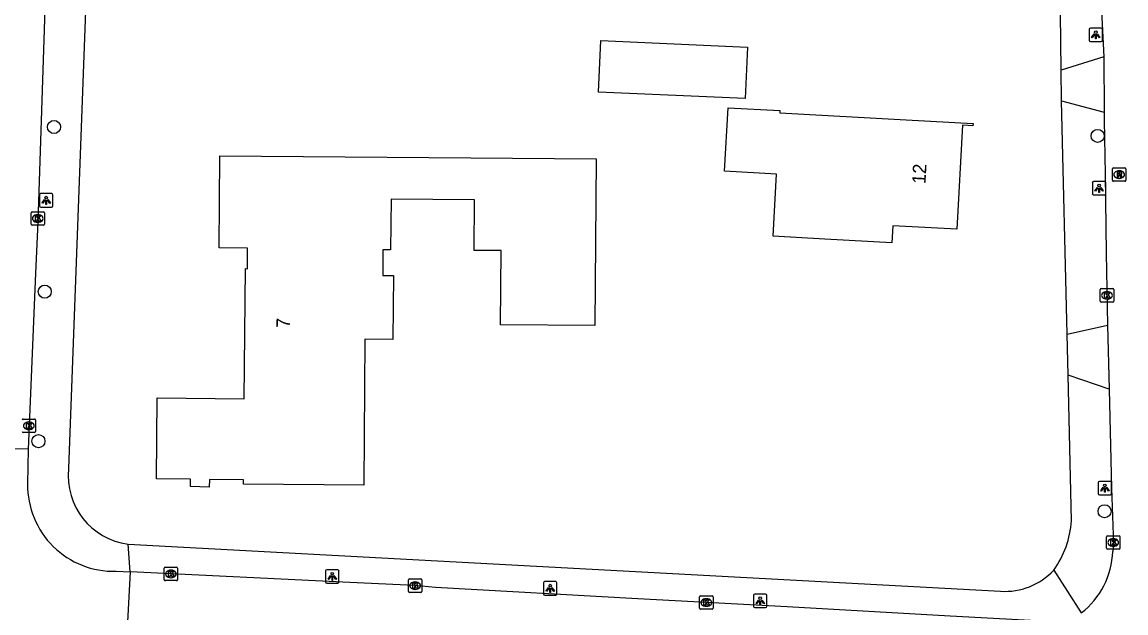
# Model space of a CAD drawing. Extents: x 161258 to 161838, y 380836 to 381727.
# Drawn here: x 161570.3 to 161652.5, y 381186.3 to 381230.3 of the extents above; entities that cross this region are included whole.
import ezdxf

# ---------------------------------------------------------------- set-up
doc = ezdxf.new("R2010")
doc.units = 0
for name, color, linetype in [('IMGEO_Boom', 7, 'Continuous'), ('IMGEO_Kolk', 7, 'Continuous'), ('IMGEO_Lichtpunt', 7, 'Continuous'), ('IMGEO_Pand', 7, 'Continuous'), ('IMGEO_Pand_nummerreeks', 7, 'Continuous'), ('IMGEO_Rijbaan_lokaal_open', 7, 'Continuous'), ('IMGEO_Rioolput', 7, 'Continuous'), ('IMGEO_Voetpad_open', 7, 'Continuous')]:
    doc.layers.add(name, color=color, linetype=linetype)

msp = doc.modelspace()

# ---------------------------------------------------------------- linework, layer by layer
at = {"layer": 'IMGEO_Boom'}
for centre in [(161572.69, 381222.454), (161650.414, 381221.789), (161571.999, 381210.202), (161571.528, 381199.077), (161650.929, 381193.862)]:
    msp.add_circle(centre, 0.489, dxfattribs=at)
at = {"layer": 'IMGEO_Kolk'}
for p, q in [((161570.979, 381215.224), (161570.979, 381216.076)), ((161571.054, 381216.15), (161571.906, 381216.15)), ((161571.467, 381215.93), (161571.492, 381215.93)), ((161571.98, 381216.076), (161571.98, 381215.224)), ((161571.906, 381215.15), (161571.054, 381215.15)), ((161571.49, 381215.37), (161571.465, 381215.37)), ((161650.609, 381209.499), (161650.609, 381210.351)), ((161650.684, 381210.425), (161651.536, 381210.425)), ((161651.097, 381210.205), (161651.122, 381210.205)), ((161651.61, 381210.351), (161651.61, 381209.499)), ((161651.536, 381209.425), (161650.684, 381209.425)), ((161651.12, 381209.645), (161651.095, 381209.645)), ((161570.387, 381200.724), (161571.239, 381200.724)), ((161571.313, 381200.65), (161571.313, 381199.798)), ((161570.823, 381199.944), (161570.798, 381199.944)), ((161570.8, 381200.504), (161570.825, 381200.504)), ((161571.239, 381199.724), (161570.387, 381199.724)), ((161651.076, 381191.107), (161651.076, 381191.959)), ((161651.151, 381192.033), (161652.003, 381192.033)), ((161651.564, 381191.813), (161651.589, 381191.813)), ((161652.077, 381191.959), (161652.077, 381191.107)), ((161652.003, 381191.033), (161651.151, 381191.033)), ((161651.587, 381191.253), (161651.562, 381191.253)), ((161580.895, 381188.771), (161580.895, 381189.623)), ((161580.97, 381189.697), (161581.822, 381189.697)), ((161581.383, 381189.477), (161581.408, 381189.477)), ((161581.896, 381189.623), (161581.896, 381188.771)), ((161581.822, 381188.697), (161580.97, 381188.697)), ((161581.406, 381188.917), (161581.381, 381188.917)), ((161599.084, 381187.9), (161599.084, 381188.752)), ((161599.159, 381188.826), (161600.011, 381188.826)), ((161599.572, 381188.606), (161599.597, 381188.606)), ((161600.085, 381188.752), (161600.085, 381187.9)), ((161600.011, 381187.826), (161599.159, 381187.826)), ((161599.595, 381188.046), (161599.57, 381188.046)), ((161620.771, 381186.642), (161620.771, 381187.494)), ((161620.846, 381187.568), (161621.698, 381187.568)), ((161621.772, 381187.494), (161621.772, 381186.642)), ((161621.282, 381186.788), (161621.257, 381186.788)), ((161621.259, 381187.348), (161621.284, 381187.348)), ((161621.698, 381186.568), (161620.846, 381186.568))]:
    msp.add_line(p, q, dxfattribs=at)
for points in [[(161570.979, 381215.224), (161570.979, 381216.076)], [(161571.054, 381216.15), (161571.906, 381216.15)], [(161571.3, 381215.85), (161571.423, 381215.85), (161571.423, 381215.699), (161571.553, 381215.85), (161571.717, 381215.85), (161571.571, 381215.699), (161571.724, 381215.45), (161571.572, 381215.45), (161571.487, 381215.614), (161571.423, 381215.547), (161571.423, 381215.45), (161571.3, 381215.45), (161571.3, 381215.85)], [(161571.98, 381216.076), (161571.98, 381215.224)], [(161571.906, 381215.15), (161571.054, 381215.15)], [(161650.609, 381209.499), (161650.609, 381210.351)], [(161650.684, 381210.425), (161651.536, 381210.425)], [(161650.93, 381210.125), (161651.053, 381210.125), (161651.053, 381209.974), (161651.183, 381210.125), (161651.347, 381210.125), (161651.201, 381209.974), (161651.354, 381209.725), (161651.202, 381209.725), (161651.117, 381209.889), (161651.053, 381209.822), (161651.053, 381209.725), (161650.93, 381209.725), (161650.93, 381210.125)], [(161651.61, 381210.351), (161651.61, 381209.499)], [(161651.536, 381209.425), (161650.684, 381209.425)], [(161570.387, 381200.724), (161571.239, 381200.724)], [(161571.313, 381200.65), (161571.313, 381199.798)], [(161570.633, 381200.424), (161570.756, 381200.424), (161570.756, 381200.273), (161570.886, 381200.424), (161571.05, 381200.424), (161570.904, 381200.273), (161571.057, 381200.024), (161570.905, 381200.024), (161570.82, 381200.188), (161570.756, 381200.121), (161570.756, 381200.024), (161570.633, 381200.024), (161570.633, 381200.424)], [(161571.239, 381199.724), (161570.387, 381199.724)], [(161651.076, 381191.107), (161651.076, 381191.959)], [(161651.151, 381192.033), (161652.003, 381192.033)], [(161651.397, 381191.733), (161651.52, 381191.733), (161651.52, 381191.582), (161651.65, 381191.733), (161651.814, 381191.733), (161651.668, 381191.582), (161651.821, 381191.333), (161651.669, 381191.333), (161651.584, 381191.497), (161651.52, 381191.43), (161651.52, 381191.333), (161651.397, 381191.333), (161651.397, 381191.733)], [(161652.077, 381191.959), (161652.077, 381191.107)], [(161652.003, 381191.033), (161651.151, 381191.033)], [(161580.895, 381188.771), (161580.895, 381189.623)], [(161580.97, 381189.697), (161581.822, 381189.697)], [(161581.216, 381189.397), (161581.339, 381189.397), (161581.339, 381189.246), (161581.469, 381189.397), (161581.633, 381189.397), (161581.487, 381189.246), (161581.64, 381188.997), (161581.488, 381188.997), (161581.403, 381189.161), (161581.339, 381189.094), (161581.339, 381188.997), (161581.216, 381188.997), (161581.216, 381189.397)], [(161581.896, 381189.623), (161581.896, 381188.771)], [(161581.822, 381188.697), (161580.97, 381188.697)], [(161599.084, 381187.9), (161599.084, 381188.752)], [(161599.159, 381188.826), (161600.011, 381188.826)], [(161599.405, 381188.526), (161599.528, 381188.526), (161599.528, 381188.375), (161599.658, 381188.526), (161599.822, 381188.526), (161599.676, 381188.375), (161599.829, 381188.126), (161599.677, 381188.126), (161599.592, 381188.29), (161599.528, 381188.223), (161599.528, 381188.126), (161599.405, 381188.126), (161599.405, 381188.526)], [(161600.085, 381188.752), (161600.085, 381187.9)], [(161600.011, 381187.826), (161599.159, 381187.826)], [(161620.771, 381186.642), (161620.771, 381187.494)], [(161620.846, 381187.568), (161621.698, 381187.568)], [(161621.772, 381187.494), (161621.772, 381186.642)], [(161621.092, 381187.268), (161621.215, 381187.268), (161621.215, 381187.117), (161621.345, 381187.268), (161621.509, 381187.268), (161621.363, 381187.117), (161621.516, 381186.868), (161621.364, 381186.868), (161621.279, 381187.032), (161621.215, 381186.965), (161621.215, 381186.868), (161621.092, 381186.868), (161621.092, 381187.268)], [(161621.698, 381186.568), (161620.846, 381186.568)]]:
    msp.add_lwpolyline(points, dxfattribs=at)
for centre, start, end in [((161571.056, 381216.074), 91.55205, 178.44795), ((161571.056, 381216.074), 91.55205, 178.44795), ((161571.904, 381216.074), 1.55205, 88.44795), ((161571.904, 381216.074), 1.55205, 88.44795), ((161571.056, 381215.226), 181.55205, 268.44795), ((161571.056, 381215.226), 181.55205, 268.44795), ((161571.904, 381215.226), 271.55205, 358.44795), ((161571.904, 381215.226), 271.55205, 358.44795), ((161650.686, 381210.349), 91.55205, 178.44795), ((161650.686, 381210.349), 91.55205, 178.44795), ((161651.534, 381210.349), 1.55205, 88.44795), ((161651.534, 381210.349), 1.55205, 88.44795), ((161650.686, 381209.501), 181.55205, 268.44795), ((161650.686, 381209.501), 181.55205, 268.44795), ((161651.534, 381209.501), 271.55205, 358.44795), ((161651.534, 381209.501), 271.55205, 358.44795), ((161570.389, 381200.648), 91.55205, 178.44795), ((161570.389, 381200.648), 91.55205, 178.44795), ((161571.237, 381200.648), 1.55205, 88.44795), ((161571.237, 381200.648), 1.55205, 88.44795), ((161570.389, 381199.8), 181.55205, 268.44795), ((161570.389, 381199.8), 181.55205, 268.44795), ((161571.237, 381199.8), 271.55205, 358.44795), ((161571.237, 381199.8), 271.55205, 358.44795), ((161651.153, 381191.957), 91.55205, 178.44795), ((161651.153, 381191.957), 91.55205, 178.44795), ((161652.001, 381191.957), 1.55205, 88.44795), ((161652.001, 381191.957), 1.55205, 88.44795), ((161651.153, 381191.109), 181.55205, 268.44795), ((161651.153, 381191.109), 181.55205, 268.44795), ((161652.001, 381191.109), 271.55205, 358.44795), ((161652.001, 381191.109), 271.55205, 358.44795), ((161580.972, 381189.621), 91.55205, 178.44795), ((161580.972, 381189.621), 91.55205, 178.44795), ((161581.82, 381189.621), 1.55205, 88.44795), ((161581.82, 381189.621), 1.55205, 88.44795), ((161580.972, 381188.773), 181.55205, 268.44795), ((161580.972, 381188.773), 181.55205, 268.44795), ((161581.82, 381188.773), 271.55205, 358.44795), ((161581.82, 381188.773), 271.55205, 358.44795), ((161599.161, 381188.75), 91.55205, 178.44795), ((161599.161, 381188.75), 91.55205, 178.44795), ((161600.009, 381188.75), 1.55205, 88.44795), ((161600.009, 381188.75), 1.55205, 88.44795), ((161599.161, 381187.902), 181.55205, 268.44795), ((161599.161, 381187.902), 181.55205, 268.44795), ((161600.009, 381187.902), 271.55205, 358.44795), ((161600.009, 381187.902), 271.55205, 358.44795), ((161620.848, 381187.492), 91.55205, 178.44795), ((161620.848, 381187.492), 91.55205, 178.44795), ((161621.696, 381187.492), 1.55205, 88.44795), ((161621.696, 381187.492), 1.55205, 88.44795), ((161620.848, 381186.644), 181.55205, 268.44795), ((161620.848, 381186.644), 181.55205, 268.44795), ((161621.696, 381186.644), 271.55205, 358.44795), ((161621.696, 381186.644), 271.55205, 358.44795)]:
    msp.add_arc(centre, 0.0765, start, end, dxfattribs=at)
for centre, major_axis, ratio, start_param, end_param in [((161571.466, 381215.65), (-0.387, 0.002), 0.722429, 4.712389, 7.853982), ((161571.491, 381215.65), (-0.39, 0.002), 0.717154, 1.570796, 4.712389), ((161651.096, 381209.925), (-0.387, 0.002), 0.722429, 4.712389, 7.853982), ((161651.121, 381209.925), (-0.39, 0.002), 0.717154, 1.570796, 4.712389), ((161570.799, 381200.224), (-0.387, 0.002), 0.722429, 4.712389, 7.853982), ((161570.824, 381200.224), (-0.39, 0.002), 0.717154, 1.570796, 4.712389), ((161651.563, 381191.533), (-0.387, 0.002), 0.722429, 4.712389, 7.853982), ((161651.588, 381191.533), (-0.39, 0.002), 0.717154, 1.570796, 4.712389), ((161581.382, 381189.197), (-0.387, 0.002), 0.722429, 4.712389, 7.853982), ((161581.407, 381189.197), (-0.39, 0.002), 0.717154, 1.570796, 4.712389), ((161599.571, 381188.326), (-0.387, 0.002), 0.722429, 4.712389, 7.853982), ((161599.596, 381188.326), (-0.39, 0.002), 0.717154, 1.570796, 4.712389), ((161621.258, 381187.068), (-0.387, 0.002), 0.722429, 4.712389, 7.853982), ((161621.283, 381187.068), (-0.39, 0.002), 0.717154, 1.570796, 4.712389)]:
    msp.add_ellipse(centre, major_axis=major_axis, ratio=ratio, start_param=start_param, end_param=end_param, dxfattribs=at)
at = {"layer": 'IMGEO_Lichtpunt'}
for p, q in [((161649.775, 381229.71), (161649.775, 381228.903)), ((161649.775, 381229.71), (161649.775, 381228.903)), ((161650.677, 381229.805), (161649.869, 381229.805)), ((161650.677, 381229.805), (161649.869, 381229.805)), ((161650.771, 381228.903), (161650.771, 381229.71)), ((161650.771, 381228.903), (161650.771, 381229.71)), ((161649.869, 381228.809), (161650.677, 381228.809)), ((161649.869, 381228.809), (161650.677, 381228.809)), ((161650.017, 381218.295), (161650.017, 381217.488)), ((161650.017, 381218.295), (161650.017, 381217.488)), ((161650.919, 381218.39), (161650.111, 381218.39)), ((161650.919, 381218.39), (161650.111, 381218.39)), ((161651.013, 381217.488), (161651.013, 381218.295)), ((161651.013, 381217.488), (161651.013, 381218.295)), ((161571.61, 381217.399), (161571.61, 381216.592)), ((161571.61, 381217.399), (161571.61, 381216.592)), ((161572.512, 381217.494), (161571.704, 381217.494)), ((161572.512, 381217.494), (161571.704, 381217.494)), ((161572.606, 381216.592), (161572.606, 381217.399)), ((161572.606, 381216.592), (161572.606, 381217.399)), ((161650.111, 381217.394), (161650.919, 381217.394)), ((161650.111, 381217.394), (161650.919, 381217.394)), ((161571.704, 381216.498), (161572.512, 381216.498)), ((161571.704, 381216.498), (161572.512, 381216.498)), ((161650.456, 381195.99), (161650.456, 381195.183)), ((161650.456, 381195.99), (161650.456, 381195.183)), ((161651.358, 381196.085), (161650.55, 381196.085)), ((161651.358, 381196.085), (161650.55, 381196.085)), ((161651.452, 381195.183), (161651.452, 381195.99)), ((161651.452, 381195.183), (161651.452, 381195.99)), ((161650.55, 381195.089), (161651.358, 381195.089)), ((161650.55, 381195.089), (161651.358, 381195.089)), ((161592.918, 381189.417), (161592.918, 381188.61)), ((161592.918, 381189.417), (161592.918, 381188.61)), ((161593.82, 381189.512), (161593.012, 381189.512)), ((161593.82, 381189.512), (161593.012, 381189.512)), ((161593.914, 381188.61), (161593.914, 381189.417)), ((161593.914, 381188.61), (161593.914, 381189.417)), ((161593.012, 381188.516), (161593.82, 381188.516)), ((161593.012, 381188.516), (161593.82, 381188.516)), ((161609.15, 381188.528), (161609.15, 381187.721)), ((161609.15, 381188.528), (161609.15, 381187.721)), ((161610.052, 381188.623), (161609.244, 381188.623)), ((161610.052, 381188.623), (161609.244, 381188.623)), ((161610.146, 381187.721), (161610.146, 381188.528)), ((161610.146, 381187.721), (161610.146, 381188.528)), ((161609.244, 381187.627), (161610.052, 381187.627)), ((161609.244, 381187.627), (161610.052, 381187.627)), ((161624.787, 381187.59), (161624.787, 381186.783)), ((161624.787, 381187.59), (161624.787, 381186.783)), ((161625.689, 381187.685), (161624.881, 381187.685)), ((161625.689, 381187.685), (161624.881, 381187.685)), ((161625.783, 381186.783), (161625.783, 381187.59)), ((161625.783, 381186.783), (161625.783, 381187.59)), ((161624.881, 381186.689), (161625.689, 381186.689)), ((161624.881, 381186.689), (161625.689, 381186.689))]:
    msp.add_line(p, q, dxfattribs=at)
for points in [[(161650.149, 381229.374), (161650.188, 381229.346), (161650, 381229.084), (161649.962, 381229.111), (161650.149, 381229.374)], [(161650.251, 381229.326), (161650.298, 381229.326), (161650.298, 381229.004), (161650.251, 381229.004), (161650.251, 381229.326)], [(161650.361, 381229.346), (161650.399, 381229.373), (161650.586, 381229.111), (161650.547, 381229.083), (161650.361, 381229.346)], [(161650.391, 381217.959), (161650.43, 381217.931), (161650.242, 381217.669), (161650.204, 381217.696), (161650.391, 381217.959)], [(161650.493, 381217.911), (161650.54, 381217.911), (161650.54, 381217.589), (161650.493, 381217.589), (161650.493, 381217.911)], [(161650.603, 381217.931), (161650.641, 381217.958), (161650.828, 381217.696), (161650.789, 381217.668), (161650.603, 381217.931)], [(161571.984, 381217.063), (161572.023, 381217.035), (161571.835, 381216.773), (161571.797, 381216.8), (161571.984, 381217.063)], [(161572.196, 381217.035), (161572.234, 381217.062), (161572.421, 381216.8), (161572.382, 381216.772), (161572.196, 381217.035)], [(161572.086, 381217.015), (161572.133, 381217.015), (161572.133, 381216.693), (161572.086, 381216.693), (161572.086, 381217.015)], [(161650.83, 381195.654), (161650.869, 381195.626), (161650.681, 381195.364), (161650.643, 381195.391), (161650.83, 381195.654)], [(161650.932, 381195.606), (161650.979, 381195.606), (161650.979, 381195.284), (161650.932, 381195.284), (161650.932, 381195.606)], [(161651.042, 381195.626), (161651.08, 381195.653), (161651.267, 381195.391), (161651.228, 381195.363), (161651.042, 381195.626)], [(161593.292, 381189.081), (161593.331, 381189.053), (161593.143, 381188.791), (161593.105, 381188.818), (161593.292, 381189.081)], [(161593.394, 381189.033), (161593.441, 381189.033), (161593.441, 381188.711), (161593.394, 381188.711), (161593.394, 381189.033)], [(161593.504, 381189.053), (161593.542, 381189.08), (161593.729, 381188.818), (161593.69, 381188.79), (161593.504, 381189.053)], [(161609.524, 381188.192), (161609.563, 381188.164), (161609.375, 381187.902), (161609.337, 381187.929), (161609.524, 381188.192)], [(161609.626, 381188.144), (161609.673, 381188.144), (161609.673, 381187.822), (161609.626, 381187.822), (161609.626, 381188.144)], [(161609.736, 381188.164), (161609.774, 381188.191), (161609.961, 381187.929), (161609.922, 381187.901), (161609.736, 381188.164)], [(161625.161, 381187.254), (161625.2, 381187.226), (161625.012, 381186.964), (161624.974, 381186.991), (161625.161, 381187.254)], [(161625.263, 381187.206), (161625.31, 381187.206), (161625.31, 381186.884), (161625.263, 381186.884), (161625.263, 381187.206)], [(161625.373, 381187.226), (161625.411, 381187.253), (161625.598, 381186.991), (161625.559, 381186.963), (161625.373, 381187.226)]]:
    msp.add_lwpolyline(points, dxfattribs=at)
for centre in [(161650.274, 381229.508), (161650.516, 381218.093), (161572.109, 381217.197), (161650.955, 381195.788), (161593.417, 381189.215), (161609.649, 381188.326), (161625.286, 381187.388)]:
    msp.add_circle(centre, 0.0994, dxfattribs=at)
for centre, start, end in [((161649.869, 381229.71), 90, 180), ((161649.869, 381229.71), 90, 180), ((161650.677, 381229.71), 0, 90), ((161650.677, 381229.71), 0, 90), ((161649.869, 381228.903), 180, 270), ((161649.869, 381228.903), 180, 270), ((161650.677, 381228.903), 270, 0), ((161650.677, 381228.903), 270, 360), ((161650.111, 381218.295), 90, 180), ((161650.111, 381218.295), 90, 180), ((161650.919, 381218.295), 0, 90), ((161650.919, 381218.295), 0, 90), ((161571.704, 381217.399), 90, 180), ((161571.704, 381217.399), 90, 180), ((161572.512, 381217.399), 0, 90), ((161572.512, 381217.399), 0, 90), ((161650.111, 381217.488), 180, 270), ((161650.111, 381217.488), 180, 270), ((161650.919, 381217.488), 270, 0), ((161650.919, 381217.488), 270, 360), ((161571.704, 381216.592), 180, 270), ((161571.704, 381216.592), 180, 270), ((161572.512, 381216.592), 270, 0), ((161572.512, 381216.592), 270, 360), ((161650.55, 381195.99), 90, 180), ((161650.55, 381195.99), 90, 180), ((161651.358, 381195.99), 0, 90), ((161651.358, 381195.99), 0, 90), ((161650.55, 381195.183), 180, 270), ((161650.55, 381195.183), 180, 270), ((161651.358, 381195.183), 270, 0), ((161651.358, 381195.183), 270, 360), ((161593.012, 381189.417), 90, 180), ((161593.012, 381189.417), 90, 180), ((161593.82, 381189.417), 0, 90), ((161593.82, 381189.417), 0, 90), ((161593.012, 381188.61), 180, 270), ((161593.012, 381188.61), 180, 270), ((161593.82, 381188.61), 270, 0), ((161593.82, 381188.61), 270, 360), ((161609.244, 381188.528), 90, 180), ((161609.244, 381188.528), 90, 180), ((161610.052, 381188.528), 0, 90), ((161610.052, 381188.528), 0, 90), ((161609.244, 381187.721), 180, 270), ((161609.244, 381187.721), 180, 270), ((161610.052, 381187.721), 270, 0), ((161610.052, 381187.721), 270, 360), ((161624.881, 381187.59), 90, 180), ((161624.881, 381187.59), 90, 180), ((161625.689, 381187.59), 0, 90), ((161625.689, 381187.59), 0, 90), ((161624.881, 381186.783), 180, 270), ((161624.881, 381186.783), 180, 270), ((161625.689, 381186.783), 270, 0), ((161625.689, 381186.783), 270, 360)]:
    msp.add_arc(centre, 0.0946, start, end, dxfattribs=at)
at = {"layer": 'IMGEO_Pand'}
for points in [[(161624.335, 381228.4), (161624.163, 381224.563), (161613.241, 381225.052), (161613.413, 381228.889), (161624.335, 381228.4)], [(161636.144, 381222.993), (161641.136, 381222.717), (161641.126, 381222.537), (161640.355, 381222.58), (161639.927, 381214.841), (161635.155, 381215.104), (161635.085, 381213.84), (161630.093, 381214.116), (161626.251, 381214.329), (161626.506, 381218.942), (161622.624, 381219.157), (161622.886, 381223.888), (161626.752, 381223.674), (161626.743, 381223.513), (161636.144, 381222.993)], [(161613.076, 381220.081), (161612.97, 381207.678), (161605.94, 381207.738), (161605.987, 381213.258), (161603.977, 381213.275), (161604.009, 381217.035), (161597.789, 381217.088), (161597.757, 381213.308), (161597.187, 381213.313), (161597.171, 381211.413), (161597.961, 381211.406), (161597.92, 381206.637), (161595.85, 381206.654), (161595.758, 381195.795), (161586.798, 381195.871), (161586.801, 381196.191), (161584.259, 381196.213), (161584.246, 381195.661), (161582.854, 381195.695), (161582.867, 381196.252), (161580.317, 381196.27), (161580.372, 381202.296), (161586.851, 381202.237), (161586.958, 381211.913), (161587.088, 381211.912), (161587.096, 381213.428), (161584.979, 381213.461), (161585.037, 381220.32), (161613.076, 381220.081)]]:
    msp.add_lwpolyline(points, dxfattribs=at)
at = {"layer": 'IMGEO_Rijbaan_lokaal_open'}
for points in [[(161571.005, 381317.713), (161571.088, 381311.972), (161571.149, 381309.659), (161571.247, 381305.925), (161571.333, 381300.008), (161571.367, 381297.22), (161571.552, 381289.803), (161571.71, 381285.385), (161571.841, 381280.385), (161571.937, 381276.234), (161572.007, 381272.353), (161572.171, 381266.916), (161572.516, 381257.53), (161572.49, 381252.317), (161572.562, 381247.819), (161571.478, 381215.409), (161571.305, 381211.541), (161570.775, 381198.479)], [(161650.551, 381240.927), (161650.682, 381233.085), (161650.693, 381231.097), (161650.875, 381227.666)], [(161650.875, 381227.666), (161650.9, 381223.559)], [(161650.9, 381223.559), (161650.904, 381222.961), (161650.974, 381218.943), (161651.056, 381213.077), (161651.149, 381207.702)], [(161651.149, 381207.702), (161651.259, 381202.942)], [(161651.259, 381202.942), (161651.452, 381195.577), (161651.582, 381191.419), (161651.539, 381190.879)], [(161570.775, 381198.479), (161563.65, 381198.628)], [(161570.775, 381198.479), (161570.721, 381195.892)], [(161577.308, 381189.397), (161578.352, 381189.346)], [(161578.352, 381189.346), (161578.149, 381185.166)], [(161646.327, 381185.682), (161639.431, 381186.067), (161627.28, 381186.753), (161616.166, 381187.333), (161601.106, 381188.192), (161599.538, 381188.329), (161594.72, 381188.551), (161578.352, 381189.346)]]:
    msp.add_lwpolyline(points, dxfattribs=at)
for centre, radius, start, end in [((161577.135, 381195.809), 6.415, 179.26189, 271.54397), ((161645.542, 381191.065), 6, 307.38392, 358.2223)]:
    msp.add_arc(centre, radius, start, end, dxfattribs=at)
at = {"layer": 'IMGEO_Rioolput'}
for p, q in [((161651.517, 381218.485), (161651.517, 381219.337)), ((161651.592, 381219.411), (161652.444, 381219.411)), ((161652.005, 381219.191), (161652.03, 381219.191)), ((161652.518, 381219.337), (161652.518, 381218.485)), ((161652.444, 381218.411), (161651.592, 381218.411)), ((161652.028, 381218.631), (161652.003, 381218.631))]:
    msp.add_line(p, q, dxfattribs=at)
for points in [[(161651.517, 381218.485), (161651.517, 381219.337)], [(161651.592, 381219.411), (161652.444, 381219.411)], [(161652.106, 381219.109), (161651.854, 381219.111), (161651.854, 381218.711)], [(161651.854, 381218.711), (161651.978, 381218.711), (161651.978, 381218.873), (161651.989, 381218.873)], [(161652.032, 381219.03), (161651.978, 381219.03), (161651.978, 381218.949)], [(161651.978, 381218.949), (161652.03, 381218.949)], [(161652.036, 381218.844), (161652.107, 381218.711), (161652.247, 381218.711), (161652.182, 381218.837)], [(161652.518, 381219.337), (161652.518, 381218.485)], [(161652.444, 381218.411), (161651.592, 381218.411)]]:
    msp.add_lwpolyline(points, dxfattribs=at)
for centre, radius, start, end in [((161651.594, 381219.335), 0.0765, 91.55205, 178.44795), ((161651.594, 381219.335), 0.0765, 91.55205, 178.44795), ((161651.988, 381218.82), 0.0533, 26.02933, 88.69889), ((161652.014, 381219.138), 0.19, 274.7715, 282.96867), ((161652.038, 381218.934), 0.0964, 77.00612, 93.18647), ((161652.052, 381218.991), 0.0378, 276.66336, 79.67722), ((161652.105, 381218.999), 0.109, 350.36119, 89.41601), ((161652.103, 381218.999), 0.112, 277.58423, 350.98172), ((161652.087, 381218.784), 0.108, 29.51342, 73.79051), ((161652.442, 381219.335), 0.0765, 1.55205, 88.44795), ((161652.442, 381219.335), 0.0765, 1.55205, 88.44795), ((161651.594, 381218.487), 0.0765, 181.55205, 268.44795), ((161651.594, 381218.487), 0.0765, 181.55205, 268.44795), ((161652.442, 381218.487), 0.0765, 271.55205, 358.44795), ((161652.442, 381218.487), 0.0765, 271.55205, 358.44795)]:
    msp.add_arc(centre, radius, start, end, dxfattribs=at)
for centre, major_axis, ratio, start_param, end_param in [((161652.004, 381218.911), (-0.387, 0.002), 0.722429, 4.712389, 7.853982), ((161652.029, 381218.911), (-0.39, 0.002), 0.717154, 1.570796, 4.712389)]:
    msp.add_ellipse(centre, major_axis=major_axis, ratio=ratio, start_param=start_param, end_param=end_param, dxfattribs=at)
at = {"layer": 'IMGEO_Voetpad_open'}
for points in [[(161573.115, 381345.957), (161575.536, 381257.867), (161575.581, 381250), (161575.075, 381232.455), (161573.778, 381197.042)], [(161647.703, 381226.675), (161647.514, 381241.517)], [(161650.875, 381227.666), (161647.703, 381226.675)], [(161647.732, 381224.403), (161647.703, 381226.675)], [(161648.137, 381207.049), (161647.732, 381224.403)], [(161647.732, 381224.403), (161650.9, 381223.559)], [(161648.137, 381207.049), (161651.149, 381207.702)], [(161648.208, 381203.989), (161648.137, 381207.049)], [(161648.461, 381193.142), (161648.208, 381203.989)], [(161651.259, 381202.942), (161648.208, 381203.989)], [(161578.21, 381191.415), (161643.179, 381187.909)], [(161578.352, 381189.346), (161578.21, 381191.415)], [(161647.155, 381189.49), (161649.185, 381186.298)]]:
    msp.add_lwpolyline(points, dxfattribs=at)
for centre, radius, start, end in [((161578.871, 381196.495), 5.122, 173.86438, 262.58576), ((161641.317, 381193.637), 7.161, 324.60952, 356.03514), ((161643.512, 381192.861), 4.963, 266.15081, 317.21827)]:
    msp.add_arc(centre, radius, start, end, dxfattribs=at)

# ---------------------------------------------------------------- texts
at = {"layer": 'IMGEO_Pand_nummerreeks'}
for s, rotation, p in [('12', 86.83452, (161637.589, 381218.202)), ('7', 88.7475, (161590.247, 381207.489))]:
    msp.add_text(s, height=1, rotation=rotation, dxfattribs=at).set_placement(p)

doc.saveas('drawing.dxf')
